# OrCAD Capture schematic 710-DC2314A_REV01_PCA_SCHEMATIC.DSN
size Custom; note: DUAL IDEAL DIODE-OR AND SINGLE HOT SWAP CONTROLLER WITH CURRENT MONITOR
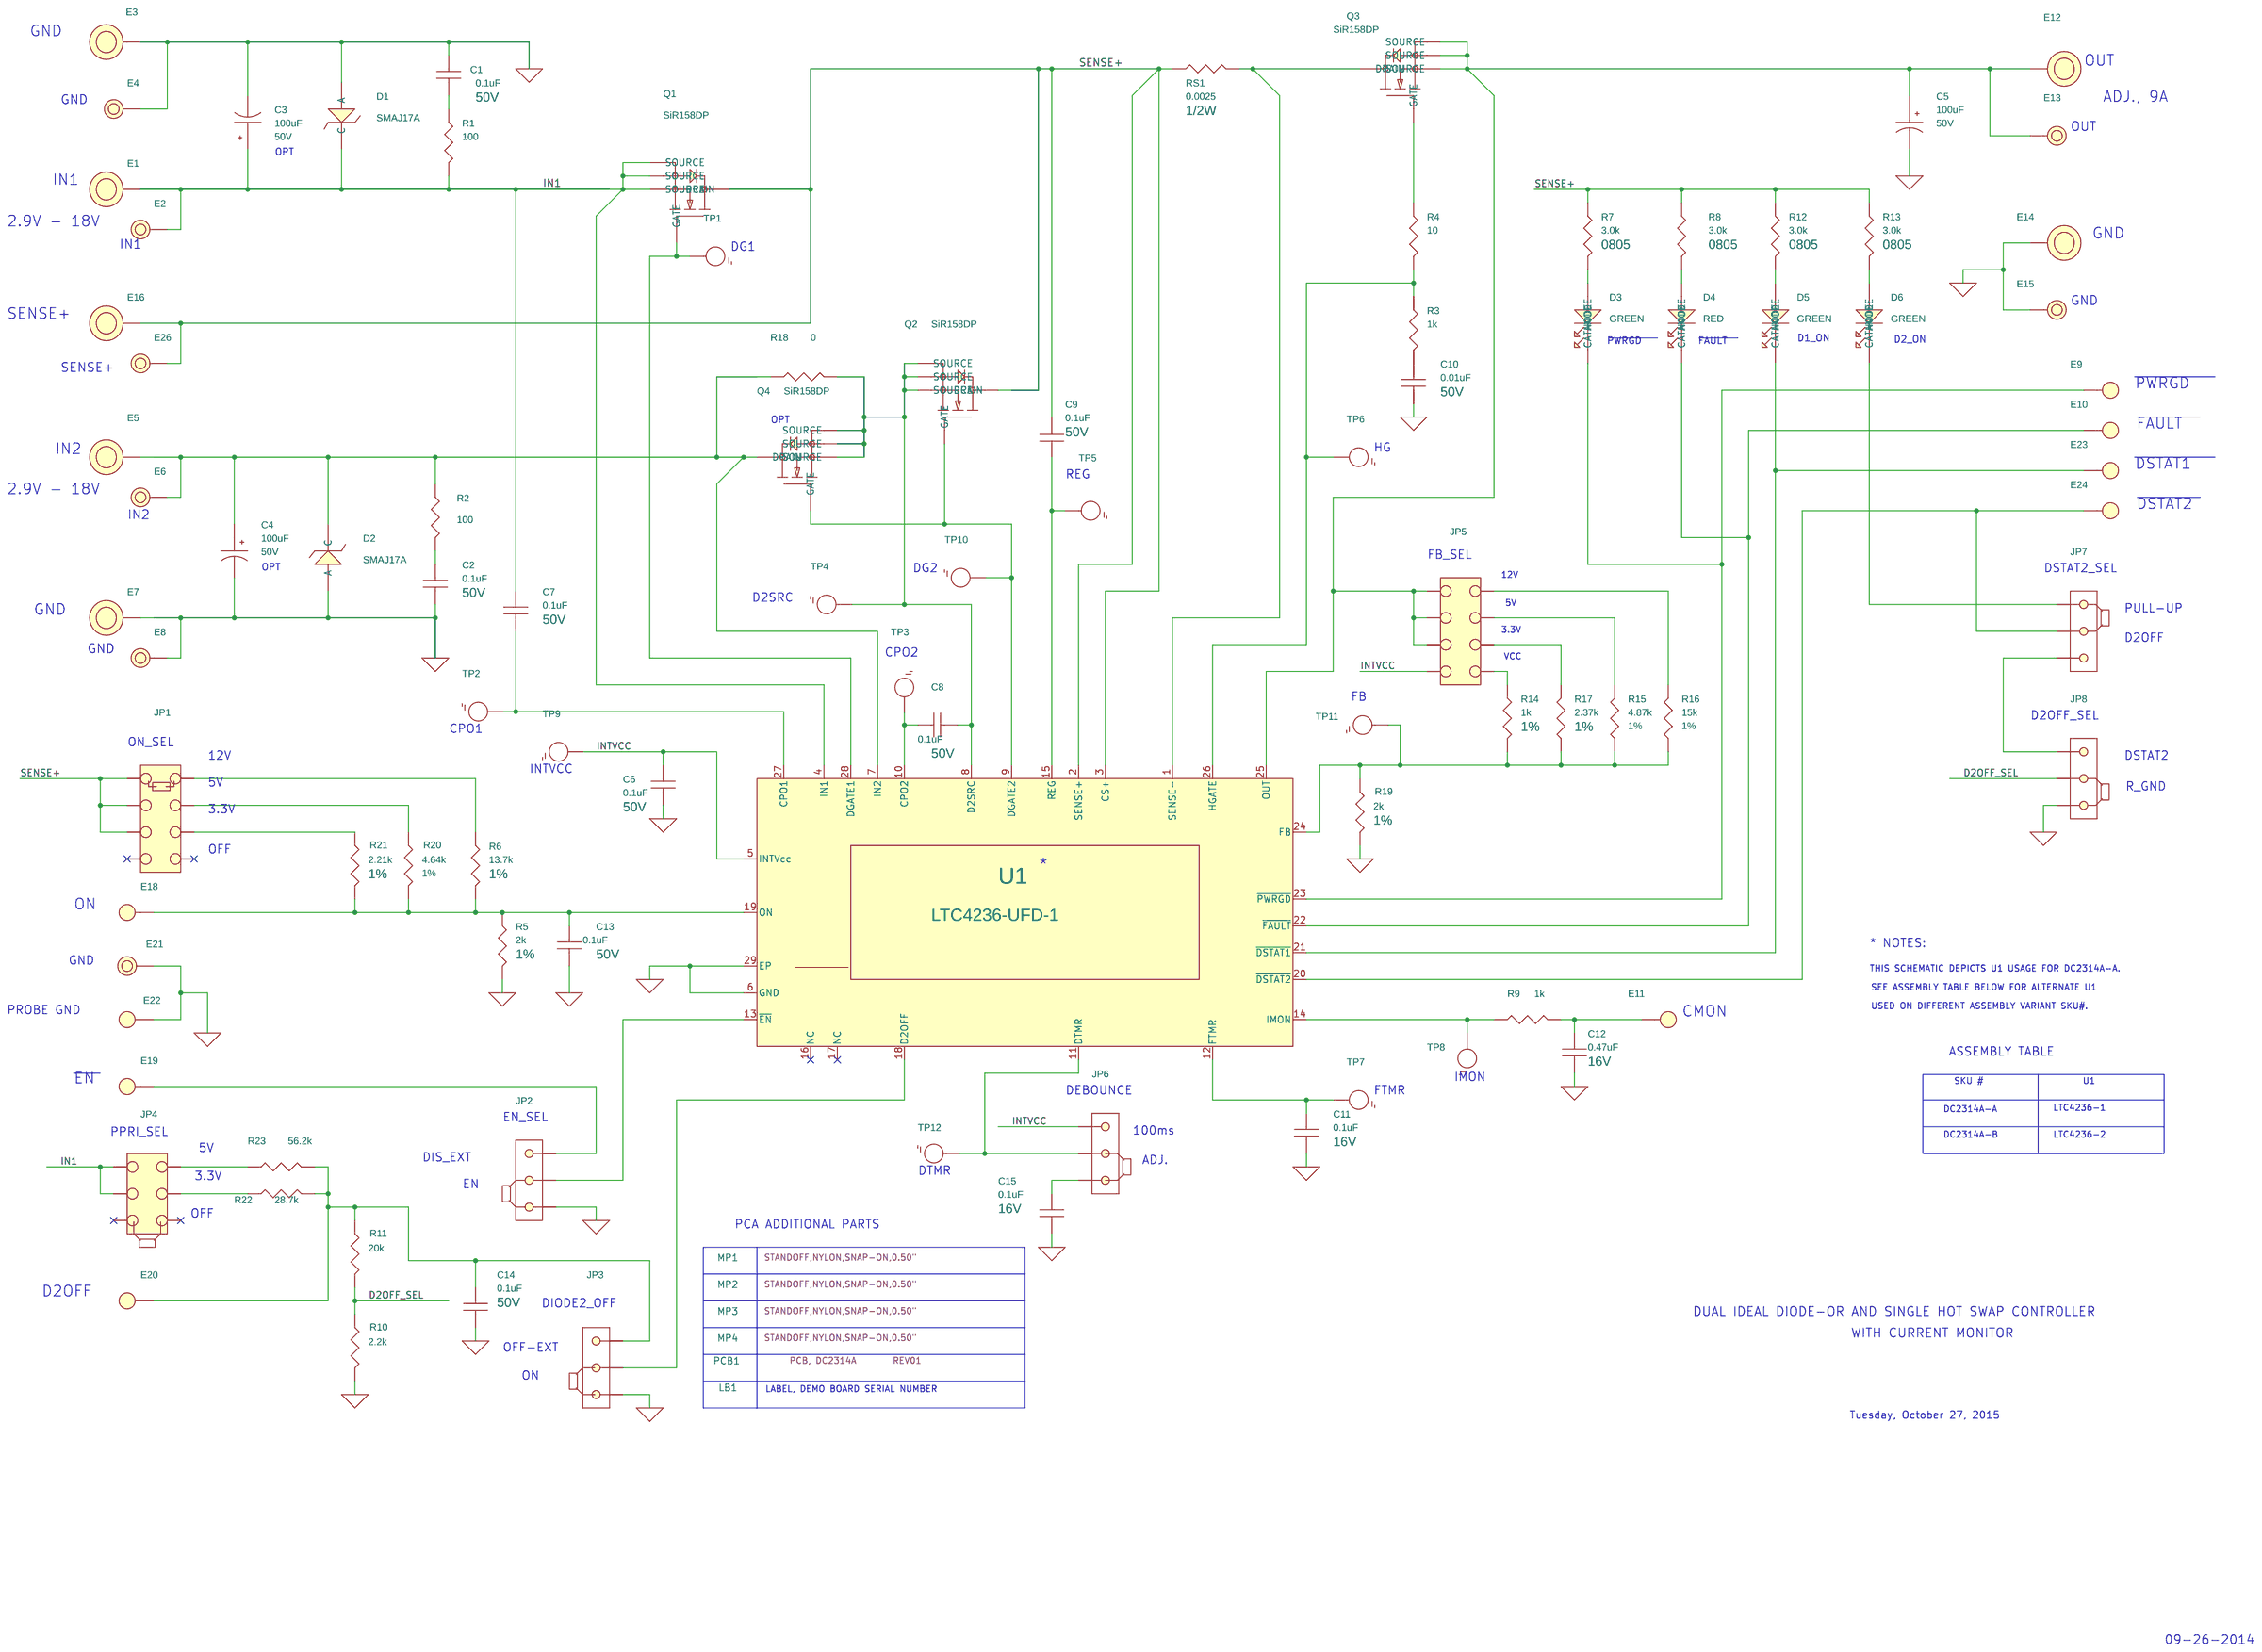
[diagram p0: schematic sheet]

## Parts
C1  0.1uF  [CC0603N]
C2  0.1uF  [CC0603N]
C3  100uF  [SUNCON-8X10.2]
C4  100uF  [SUNCON-8X10.2]
C5  100uF  [SUNCON-8X10.2]
C6  0.1uF  [CC0603N]
C7  0.1uF  [CC0603N]
C8  0.1uF  [CC0603N]
C9  0.1uF  [CC0603N]
C10  0.01uF  [CC0603N]
C11  0.1uF  [CC0603N]
C12  0.47uF  [CC0603N]
C13  0.1uF  [CC0603N]
C14  0.1uF  [CC0603N]
C15  0.1uF  [CC0603N]
D1  SMAJ17A  [SMA]
D2  SMAJ17A  [SMA]
D3  GREEN  [ROHM_SML-010]
D4  RED  [ROHM_SML-010]
D5  GREEN  [ROHM_SML-010]
D6  GREEN  [ROHM_SML-010]
E1  BANANA JACK  [KEY-575-4]
E2  TEST POINT  [MILLMAX2501]
E3  BANANA JACK  [KEY-575-4]
E4  TEST POINT  [MILLMAX2501]
E5  BANANA JACK  [KEY-575-4]
E6  TEST POINT  [MILLMAX2501]
E7  BANANA JACK  [KEY-575-4]
E8  TEST POINT  [MILLMAX2501]
E9  TEST POINT  [MILLMAX2308]
E10  TEST POINT  [MILLMAX2308]
E11  TEST POINT  [MILLMAX2308]
E12  BANANA JACK  [KEY-575-4]
E13  TEST POINT  [MILLMAX2501]
E14  BANANA JACK  [KEY-575-4]
E15  TEST POINT  [MILLMAX2501]
E16  BANANA JACK  [KEY-575-4]
E18  TEST POINT  [MILLMAX2308]
E19  TEST POINT  [MILLMAX2308]
E20  TEST POINT  [MILLMAX2308]
E21  TEST POINT  [MILLMAX2501]
E22  TEST POINT  [MILLMAX2308]
E23  TEST POINT  [MILLMAX2308]
E24  TEST POINT  [MILLMAX2308]
E26  TEST POINT  [MILLMAX2501]
JP1  HEADER  [HD2X4-079]
JP2  HEADER  [JP3X1/079]
JP3  HEADER  [JP3X1/079]
JP4  HEADER  [HD2X3-079]
JP5  HEADER  [HD2X4-079]
JP6  HEADER  [JP3X1/079]
JP7  HEADER  [JP3X1/079]
JP8  HEADER  [JP3X1/079]
LB1  LABEL  [895-0154_REV01]
MP1  STANDOFF  [MTG-8831]
MP2  STANDOFF  [MTG-8831]
MP3  STANDOFF  [MTG-8831]
MP4  STANDOFF  [MTG-8831]
PCB1  PCB, DC2314A  [MECHANICAL_PART]
Q1  SiR158DP  [VISHAY_PPAK_SO-8]
Q2  SiR158DP  [VISHAY_PPAK_SO-8]
Q3  SiR158DP  [VISHAY_PPAK_SO-8]
Q4  SiR158DP  [VISHAY_PPAK_SO-8]
R1  100  [CR0603N]
R2  100  [CR0603N]
R3  1k  [CR0603N]
R4  10  [CR0603N]
R5  2k  [CR0603N]
R6  13.7k  [CR0603N]
R7  3.0k  [CR0805N]
R8  3.0k  [CR0805N]
R9  1k  [CR0603N]
R10  2.2k  [CR0603N]
R11  20k  [CR0603N]
R12  3.0k  [CR0805N]
R13  3.0k  [CR0805N]
R14  1k  [CR0603N]
R15  4.87k  [CR0603N]
R16  15k  [CR0603N]
R17  2.37k  [CR0603N]
R18  0  [VISHAY_WSL2010]
R19  2k  [CR0603N]
R20  4.64k  [CR0603N]
R21  2.21k  [CR0603N]
R22  28.7k  [CR0603N]
R23  56.2k  [CR0603N]
RS1  0.0025  [VISHAY_WSL2010]
TP1  TEST PAD  [PADSTYLE2]
TP2  TEST PAD  [PADSTYLE2]
TP3  TEST PAD  [PADSTYLE2]
TP4  TEST PAD  [PADSTYLE2]
TP5  TEST PAD  [PADSTYLE2]
TP6  TEST PAD  [PADSTYLE2]
TP7  TEST PAD  [PADSTYLE2]
TP8  TEST PAD  [PADSTYLE2]
TP9  TEST PAD  [PADSTYLE2]
TP10  TEST PAD  [PADSTYLE2]
TP11  TEST PAD  [PADSTYLE2]
TP12  TEST PAD  [PADSTYLE2]
U1  LTC4236-UFD-1  [LTC-UFD-28-1712]
XJP1  SHUNT
XJP2  SHUNT
XJP3  SHUNT
XJP4  SHUNT
XJP5  SHUNT
XJP7  SHUNT
XJP8  SHUNT
XJP9  SHUNT

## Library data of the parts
C1 C2 C6-C9 C13 C14 = CAP: CAP.,0.1uF,X7R,50V,10%,0603; CLASS: DISCRETE; Dielectric Type: X7R; Manufacturer: AVX; Manufacturer PN: 06035C104KAT2A; PART_NUMBER: 150-3082; Package Size: 0603; Rated Voltage: 50V; Tolerance: 10%
C3-C5 = CAP_P: CAP.,100uF,ALUM. ELECT.,50V,20%,SMD; BOM Notes: C3,C4 OPTIONAL; CLASS: DISCRETE; Dielectric Type: ALUM. ELECT.; Manufacturer: SUN ELECTRONIC INDUSTRIES CORP; Manufacturer PN: 50CE100BS; PART_NUMBER: 150-3085; Package Size: SMD; Rated Voltage: 50V; Tolerance: 20%
C10 = CAP: CAP.,0.01uF,X7R,50V,10%,0603; CLASS: DISCRETE; Dielectric Type: X7R; Manufacturer: AVX; Manufacturer PN: 06035C103KAT2A; PART_NUMBER: 150-3030; Package Size: 0603; Rated Voltage: 50V; Tolerance: 10%
C11 C15 = CAP: CAP.,0.1uF,X7R,16V,10%,0603; CLASS: DISCRETE; Dielectric Type: X7R; Manufacturer: AVX; Manufacturer PN: 0603YC104KAT2A; PART_NUMBER: 150-0164; Package Size: 0603; Rated Voltage: 16V; Tolerance: 10%
C12 = CAP: CAP.,0.47uF,X7R,16V,10%,0603; CLASS: DISCRETE; Dielectric Type: X7R; Manufacturer: AVX; Manufacturer PN: 0603YC474KAT2A; PART_NUMBER: 150-3353; Package Size: 0603; Rated Voltage: 16V; Tolerance: 10%
D1 D2 = DIODE_TVS_B: DIODE,TVS, UNI-DIR.,17V,400W,2PIN SMA; CLASS: DISCRETE; Manufacturer: DIODES INC; Manufacturer PN: SMAJ17A-13-F; PART_NUMBER: 210-0066; Rated Voltage: 17V
D3 D5 D6 = LED_GREEN: LED,GREEN,CLEAR,3020 (1208); CLASS: DISCRETE; FPLIST: LED_1208(3020METRIC),ROHM_SML-010; Manufacturer: ROHM; Manufacturer PN: SML-012P8TT86; PART_NUMBER: 270-0075
D4 = LED_RED: LED,RED,CLEAR,3020 (1208); CLASS: DISCRETE; FPLIST: LED_1208(3020METRIC),ROHM_SML-010; Manufacturer: ROHM; Manufacturer PN: SML-012V8TT86; PART_NUMBER: 270-0077
E1 E3 E5 E7 E12 E14 E16 = BANANA_KEYSTONE-575-4: CONN.,BANANA JACK,FEMALE,THT,NON-INSULATED, SWAGE; CLASS: IO; Manufacturer PN: 575-4; PART_NUMBER: 250-0428
E2 E4 E6 E8 E13 E15 E21 E26 = TESTPOINT_.219_MILL-MAX_2501: TEST POINT,TURRET,0.094",MTG. HOLE; CLASS: IO; Manufacturer: MILL-MAX; Manufacturer PN: 2501-2-00-80-00-00-07-0; PART_NUMBER: 260-0003
E9-E11 E18-E20 E22-E24 = TEST_POINT_.156_MILL-MAX_2308: TEST POINT,TURRET,0.064" MTG. HOLE; CLASS: IO; Manufacturer PN: 2308-2-00-80-00-00-07-0; PART_NUMBER: 260-0004
JP1 JP5 = HEADER_2X4_.079: CONN.,HEADER,2X4,2mm,THT; CLASS: IO; Manufacturer: 3M, RS HUGHES; Manufacturer PN: 951208-8622-AR; PART_NUMBER: 250-0556
JP2 JP3 JP6-JP8 = 3_PIN_HEADER_.079_SINGLE_ROW_C: CONN.,HEADER,MALE,1X3,2mm,THT; CLASS: IO; Manufacturer PN: TMM-103-02-L-S; PART_NUMBER: 250-0422
JP4 = HEADER_2X3_.079: CONN.,HEADER,2X3,2mm,THT; CLASS: IO; Manufacturer PN: TMM-103-02-L-D; PART_NUMBER: 250-0423
LB1 = BLANK_LABEL: LABEL SPEC, DEMO BOARD SERIAL NUMBER; Manufacturer: BRADY; Manufacturer PN: THT-96-717-10; PART_NUMBER: 895-0154
MP1-MP4 = BLANK_MECHANICAL_PART: STANDOFF,NYLON,SNAP-ON,0.50"; CLASS: MECHANICAL PART; Manufacturer: KEYSTONE; Manufacturer PN: 8833; PART_NUMBER: 763-0007
PCB1 = BLANK_PCB_PART: BOM Notes: REV01; CLASS: PCB; Manufacturer: MAO BANG; Manufacturer PN: 600-DC2314A; PART_NUMBER: 600-DC2314A
Q1-Q4 = SiR158DP_VISHAY: XSTR.,MOSFET, N-CHAN.,30V,40A,PPAK SO; CLASS: DISCRETE; Manufacturer: VISHAY; Manufacturer PN: SiR158DP-T1-GE3; PART_NUMBER: 240-0096
R1 R2 = RES: RES.,100 OHMS,1%,1/10W,0603; CLASS: DISCRETE; Manufacturer: YAGEO; Manufacturer PN: RC0603FR-07100RL; PART_NUMBER: 100-0150; Package Size: 0603; Rated Power: 1/10W; Temperature Coefficient: 100ppm/C; Tolerance: 1%
R3 R9 = RES: RES.,1k OHM,1%,1/10W,0603; CLASS: DISCRETE; FPLIST: CR0603N,CR0603L,CR0603M; Manufacturer: NIC; Manufacturer PN: NRC06F1001TRF; PART_NUMBER: 100-2422; Package Size: 0603; Rated Power: 1/10W; Temperature Coefficient: 100ppm; Tolerance: 1%
R4 = RES: RES.,10 OHMS,1%,1/10W,0603; CLASS: DISCRETE; Manufacturer: PANASONIC; Manufacturer PN: ERJ3EKF10R0V; PART_NUMBER: 100-2306; Package Size: 0603; Rated Power: 1/10W; Temperature Coefficient: 100ppm/C; Tolerance: 1%
R5 R19 = RES: RES.,2k OHMS,1%,1/10W,0603; CLASS: DISCRETE; Manufacturer: NIC; Manufacturer PN: NRC06F2001TRF; PART_NUMBER: 100-2313; Package Size: 0603; Rated Power: 1/10W; Temperature Coefficient: 100ppm/C; Tolerance: 1%
R6 = RES: RES.,13.7k OHMS,1%,1/10W,0603; CLASS: DISCRETE; Manufacturer: PANASONIC; Manufacturer PN: ERJ3EKF1372V; PART_NUMBER: 100-2556; Package Size: 0603; Rated Power: 1/10W; Temperature Coefficient: 100ppm/C; Tolerance: 1%
R7 R8 R12 R13 = RES: RES.,3.0k OHMS,1%,1/8W,0805; CLASS: DISCRETE; Manufacturer: KOA SPEER; Manufacturer PN: RK73H2ATTDD3001F; PART_NUMBER: 100-2449; Package Size: 0805; Rated Power: 1/8W; Temperature Coefficient: 100ppm/C; Tolerance: 1%
R10 = RES: RES.,2.2k OHMS,1%,1/10W,0603; CLASS: DISCRETE; Manufacturer: YAGEO; Manufacturer PN: RC0603FR-072K2L; PART_NUMBER: 100-2116; Package Size: 0603; Rated Power: 1/10W; Temperature Coefficient: +/-100PPM; Tolerance: 1%
R11 = RES: RES.,20k OHMS,1%,1/10W,0603; CLASS: DISCRETE; Manufacturer: YAGEO; Manufacturer PN: RC0603FR-0720KL; PART_NUMBER: 100-2117; Package Size: 0603; Rated Power: 1/10W; Temperature Coefficient: +/-100PPM; Tolerance: 1%
R14 = RES: RES.,1k OHM,1%,1/10W,0603; CLASS: DISCRETE; Manufacturer: NIC; Manufacturer PN: NRC06F1001TRF; PART_NUMBER: 100-2422; Package Size: 0603; Rated Power: 1/10W; Temperature Coefficient: 100ppm; Tolerance: 1%
R15 = RES: RES.,4.87k OHMS,1%,1/10W,0603; CLASS: DISCRETE; FPLIST: CR0603N,CR0603L,CR0603M; Manufacturer: PANASONIC; Manufacturer PN: ERJ3EKF4871V; PART_NUMBER: 100-0040; Package Size: 0603; Rated Power: 1/10W; Temperature Coefficient: 100ppm/C; Tolerance: 1%
R16 = RES: RES.,15k OHMS,1%,1/10W,0603; CLASS: DISCRETE; FPLIST: CR0603N,CR0603L,CR0603M; Manufacturer: NIC; Manufacturer PN: NRC06F1502TRF; PART_NUMBER: 100-2757; Package Size: 0603; Rated Power: 1/10W; Temperature Coefficient: 100ppm/C; Tolerance: 1%
R17 = RES: RES.,2.37k OHMS,1%,1/10W,0603; CLASS: DISCRETE; Manufacturer: VISHAY; Manufacturer PN: CRCW06032K37FKEA; PART_NUMBER: 100-2118; Package Size: 0603; Rated Power: 1/10W; Temperature Coefficient: +/-100PPM; Tolerance: 1%
R18 = RES: RES.,Metal Strip,0 OHMS,1%,2010; CLASS: DISCRETE; Manufacturer: VISHAY; Manufacturer PN: WSL201000000ZEA9; PART_NUMBER: 100-2028; Package Size: 2010; Tolerance: 1%
R20 = RES: RES.,4.64k OHMS,1%,1/10W,0603; CLASS: DISCRETE; FPLIST: CR0603N,CR0603L,CR0603M; Manufacturer: VISHAY; Manufacturer PN: CRCW06034K64FKEA; PART_NUMBER: 100-0318; Package Size: 0603; Rated Power: 1/10W; Temperature Coefficient: 100ppm/C; Tolerance: 1%
R21 = RES: RES.,2.21k OHMS,1%,1/10W,0603; CLASS: DISCRETE; Manufacturer: VISHAY; Manufacturer PN: CRCW06032K21FKEA; PART_NUMBER: 100-2115; Package Size: 0603; Rated Power: 1/10W; Temperature Coefficient: +/-100PPM; Tolerance: 1%
R22 = RES: RES.,28.7k OHMS,1%,1/10W,0603; CLASS: DISCRETE; FPLIST: CR0603N,CR0603L,CR0603M; Manufacturer: VISHAY; Manufacturer PN: CRCW060328K7FKEA; PART_NUMBER: 100-2450; Package Size: 0603; Rated Power: 1/10W; Temperature Coefficient: 100ppm/C; Tolerance: 1%
R23 = RES: RES.,56.2k OHMS,1%,1/10W,0603; CLASS: DISCRETE; FPLIST: CR0603N,CR0603L,CR0603M; Manufacturer: VISHAY; Manufacturer PN: CRCW060356K2FKEA; PART_NUMBER: 100-2697; Package Size: 0603; Rated Power: 1/10W; Temperature Coefficient: 100ppm/C; Tolerance: 1%
RS1 = RES: RES.,SENSE,0.0025 OHMS,1%,1/2W,2010; CLASS: DISCRETE; Manufacturer: VISHAY; Manufacturer PN: WSL20102L500FEA; PART_NUMBER: 100-2763; Package Size: 2010; Rated Power: 1/2W; Temperature Coefficient: 275ppm; Tolerance: 1%
TP1-TP12 = TESTPOINT_FILLED_CIRCLE: TESTPOINT, PCB COPPER FEATURE; CLASS: IO; FPLIST: PADSTYLE1,PADSTYLE2,PADSTYLE3,PADSTYLE4,PADSTYLE5,PADSTYLE6,PADSTYLE7,PADSTYLE8; Manufacturer: N/A; Manufacturer PN: N/A; PART_NUMBER: PCBPADS-1
U1 = LTC4236-UFD: IC,IDEAL DIODE,QFN, HOT SWAP CONTROLLER; CLASS: IC; Manufacturer: LINEAR TECHNOLOGY; Manufacturer PN: LTC4236IUFD-1#PDF; PART_NUMBER: 550-0075
XJP1 XJP5 = SHUNT_2MM_C: CONN.,SHUNT,FEMALE,2 POS,2mm; CLASS: IO; Manufacturer PN: 2SN-BK-G; PART_NUMBER: 250-0419
XJP2-XJP4 XJP7-XJP9 = SHUNT_2MM: CONN.,SHUNT,FEMALE,2 POS,2mm; CLASS: IO; Manufacturer PN: 2SN-BK-G; PART_NUMBER: 250-0419

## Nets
GND: C1.1 C2.2 C3.2 C4.2 C5.2 C6.2 C10.2 C11.2 C12.2 C13.2 C14.2 C15.2 D1.2(A) D2.2(A) E3.1 E4.1 E7.1 E8.1 E14.1 E15.1 E21.1 E22.1(A) JP2.3 JP3.3 JP8.3 R5.2 R10.2 R19.2 U1.6(GND) U1.29(EP)
D2OFF_SEL: JP8.2 R10.1 R11.2
IN1: C3.1 C7.1 D1.1(C) E1.1 E2.1 JP4.1 JP4.3 Q1.1(SOURCE) Q1.2(SOURCE) Q1.3(SOURCE) R1.2 U1.4(IN1)
INTVCC: C6.1 JP5.7 JP6.1 TP9.1 U1.5(INTVcc)
SENSE+: C9.2 E16.1 E26.1 JP1.1 JP1.3 JP1.5 Q1.5(DRAIN) Q2.5(DRAIN) R7.1 R8.1 R12.1 R13.1 RS1.1 U1.2(SENSE+) U1.3(CS+)
N19974362: C4.1 D2.1(C) E5.1 E6.1 Q4.5(DRAIN) R2.1 R18.1 U1.7(IN2)
N19974805: Q1.4(GATE) TP1.1 U1.28(DGATE1)
N19975212: C2.1 R2.2
N19975319: C8.2 Q2.1(SOURCE) Q2.2(SOURCE) Q2.3(SOURCE) Q4.1(SOURCE) Q4.2(SOURCE) Q4.3(SOURCE) R18.2 TP4.1 U1.8(D2SRC)
N19975492: C7.2 TP2.1 U1.27(CPO1)
N19977431: Q3.4(GATE) R4.1
N19977451: R3.1 R4.2 TP6.1 U1.26(HGATE)
N19977532: C5.1 E12.1 E13.1 JP5.1 JP5.3 JP5.5 Q3.1(SOURCE) Q3.2(SOURCE) Q3.3(SOURCE) U1.25(OUT)
N19978242: D3.2(ANODE) R7.2
N19978266: D4.2(ANODE) R8.2
N19978715: D4.1(CATHODE) E10.1(A) U1.22(~{FAULT})
N19978781: C11.1 TP7.1 U1.12(FTMR)
N19978947: C12.1 E11.1(A) R9.2
N19980802: JP4.2 R23.1
N19981217: JP2.2 U1.13(~{EN})
N19981269: E19.1(A) JP2.1
N19981415: C13.1 E18.1(A) R5.1 R6.2 R20.2 R21.2 U1.19(ON)
N19981825: JP1.2 R6.1
N19991688: C1.2 R1.1
N20055794: C8.1 TP3.1 U1.10(CPO2)
N20056944: Q2.4(GATE) Q4.4(GATE) TP10.1 U1.9(DGATE2)
N20057321: C9.1 TP5.1 U1.15(REG)
N20060868: Q3.5(DRAIN) RS1.2 U1.1(SENSE-)
N20064225: D5.2(ANODE) R12.2
N20064260: D6.2(ANODE) R13.2
N20064972: D5.1(CATHODE) E23.1(A) U1.21(~{DSTAT1})
N20064981: E24.1(A) JP7.2 U1.20(~{DSTAT2})
N20065020: D3.1(CATHODE) E9.1(A) U1.23(~{PWRGD})
N20090205: JP5.8 R14.1
N20090209: JP5.6 R17.2
N20090214: JP5.4 R15.2
N20090229: JP5.2 R16.2
N20090234: R14.2 R15.1 R16.1 R17.1 R19.1 TP11.1 U1.24(FB)
N20108622: R9.1 TP8.1 U1.14(IMON)
N20111692: JP6.2 TP12.1 U1.11(DTMR)
N20113247: C15.1 JP6.3
N20114403: JP1.4 R20.1
N20114758: JP1.6 R21.1
N20117489: JP4.4 R22.1
N20117494: C14.1 E20.1(A) JP3.1 R11.1 R22.2 R23.2
N20118973: JP3.2 U1.18(D2OFF)
N20121100: D6.1(CATHODE) JP7.1
N20121199: JP7.3 JP8.1
N20173135: C10.1 R3.2

Not connected (* = marked no-connect by the designer): JP1 7* 8*; JP4 5* 6*; U1 16(NC)* 17(NC)*

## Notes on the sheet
- GND
- OUT
- GND
- ADJ., 9A
- OUT
- OPT
- IN1
- 2.9V - 18V
- GND
- IN1
- DG1
- SENSE+
- GND
- PWRGD
- FAULT
- D1_ON
- D2_ON
- SENSE+
- PWRGD
- OPT
- FAULT
- IN2
- HG
- DSTAT1
- REG
- 2.9V - 18V
- DSTAT2
- IN2
- FB_SEL
- OPT
- DG2
- 12V
- DSTAT2_SEL
- GND
- D2SRC
- 5V
- PULL-UP
- 3.3V
- D2OFF
- GND
- CPO2
- VCC
- FB
- D2OFF_SEL
- CPO1
- ON_SEL
- 12V
- DSTAT2
- INTVCC
- 5V
- R_GND
- 3.3V
- OFF
- *
- ON
- * NOTES:
- GND
- THIS SCHEMATIC DEPICTS U1 USAGE FOR DC2314A-A.
- SEE ASSEMBLY TABLE BELOW FOR ALTERNATE U1
- USED ON DIFFERENT ASSEMBLY VARIANT SKU#.
- PROBE GND
- CMON
- ASSEMBLY TABLE
- EN
- IMON
- SKU #
- U1
- DEBOUNCE
- FTMR
- EN_SEL
- DC2314A-A
- LTC4236-1
- PPRI_SEL
- 100ms
- 5V
- DC2314A-B
- LTC4236-2
- DIS_EXT
- ADJ.
- 3.3V
- DTMR
- EN
- OFF
- PCA ADDITIONAL PARTS
- D2OFF
- DIODE2_OFF
- DUAL IDEAL DIODE-OR AND SINGLE HOT SWAP CONTROLLER
- WITH CURRENT MONITOR
- OFF-EXT
- ON
- LABEL, DEMO BOARD SERIAL NUMBER
- Tuesday, October 27, 2015
- 09-26-2014
